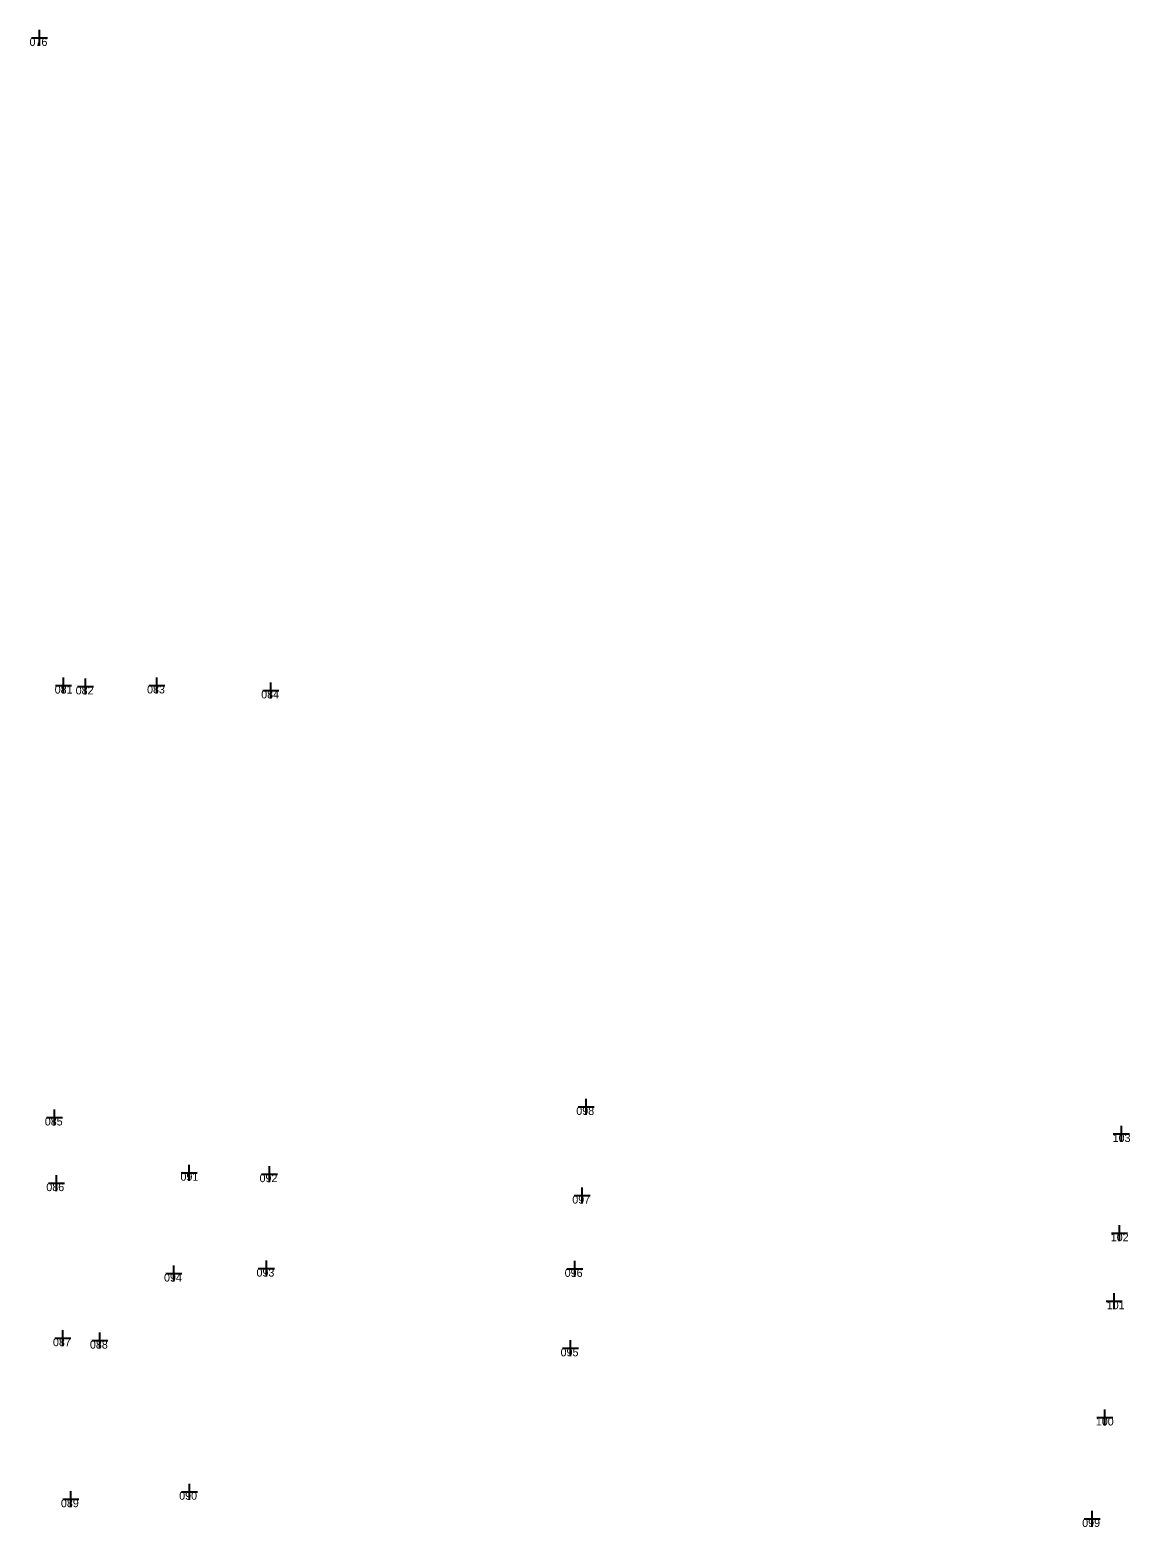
# Model space of a CAD drawing. Extents: x -706655 to -706193, y -1036183 to -1034979.
# Drawn here: x -706408.8 to -706340.1, y -1035526.2 to -1035432.7 of the extents above; entities that cross this region are included whole.
import ezdxf

# ---------------------------------------------------------------- set-up
doc = ezdxf.new("R2010")
doc.units = 0
doc.layers.add('čísla bodu', color=7, linetype='Continuous')

msp = doc.modelspace()

# ---------------------------------------------------------------- linework, layer by layer
at = {"layer": 'čísla bodu'}
for p, q in [((-706408.2, -1035433.66), (-706408.2, -1035432.66)), ((-706408.7, -1035433.16), (-706407.7, -1035433.16)), ((-706408.2, -1035433.16), (-706408.2, -1035433.16)), ((-706407.21, -1035473.62), (-706406.21, -1035473.62)), ((-706406.71, -1035474.12), (-706406.71, -1035473.12)), ((-706406.71, -1035473.62), (-706406.71, -1035473.62)), ((-706405.83, -1035473.67), (-706404.83, -1035473.67)), ((-706405.33, -1035474.17), (-706405.33, -1035473.17)), ((-706405.33, -1035473.67), (-706405.33, -1035473.67)), ((-706401.37, -1035473.61), (-706400.37, -1035473.61)), ((-706400.87, -1035474.11), (-706400.87, -1035473.11)), ((-706400.87, -1035473.61), (-706400.87, -1035473.61)), ((-706394.24, -1035473.92), (-706393.24, -1035473.92)), ((-706393.74, -1035474.42), (-706393.74, -1035473.42)), ((-706393.74, -1035473.92), (-706393.74, -1035473.92)), ((-706407.26, -1035501.1), (-706407.26, -1035500.1)), ((-706374.55, -1035499.94), (-706373.55, -1035499.94)), ((-706374.05, -1035500.44), (-706374.05, -1035499.44)), ((-706374.05, -1035499.94), (-706374.05, -1035499.94)), ((-706407.76, -1035500.6), (-706406.76, -1035500.6)), ((-706407.26, -1035500.6), (-706407.26, -1035500.6)), ((-706340.61, -1035502.13), (-706340.61, -1035501.13)), ((-706341.11, -1035501.63), (-706340.11, -1035501.63)), ((-706340.61, -1035501.63), (-706340.61, -1035501.63)), ((-706398.85, -1035504.55), (-706398.85, -1035503.55)), ((-706393.84, -1035504.64), (-706393.84, -1035503.64)), ((-706407.65, -1035504.7), (-706406.65, -1035504.7)), ((-706407.15, -1035505.2), (-706407.15, -1035504.2)), ((-706407.15, -1035504.7), (-706407.15, -1035504.7)), ((-706399.35, -1035504.05), (-706398.35, -1035504.05)), ((-706398.85, -1035504.05), (-706398.85, -1035504.05)), ((-706394.34, -1035504.14), (-706393.34, -1035504.14)), ((-706393.84, -1035504.14), (-706393.84, -1035504.14)), ((-706374.8, -1035505.48), (-706373.8, -1035505.48)), ((-706374.3, -1035505.98), (-706374.3, -1035504.98)), ((-706374.3, -1035505.48), (-706374.3, -1035505.48)), ((-706340.73, -1035508.33), (-706340.73, -1035507.33)), ((-706341.23, -1035507.83), (-706340.23, -1035507.83)), ((-706340.73, -1035507.83), (-706340.73, -1035507.83)), ((-706394.03, -1035510.54), (-706394.03, -1035509.54)), ((-706374.76, -1035510.56), (-706374.76, -1035509.56)), ((-706400.31, -1035510.35), (-706399.31, -1035510.35)), ((-706399.81, -1035510.85), (-706399.81, -1035509.85)), ((-706399.81, -1035510.35), (-706399.81, -1035510.35)), ((-706394.53, -1035510.04), (-706393.53, -1035510.04)), ((-706394.03, -1035510.04), (-706394.03, -1035510.04)), ((-706375.26, -1035510.06), (-706374.26, -1035510.06)), ((-706374.76, -1035510.06), (-706374.76, -1035510.06)), ((-706341.55, -1035512.08), (-706340.55, -1035512.08)), ((-706341.05, -1035512.58), (-706341.05, -1035511.58)), ((-706341.05, -1035512.08), (-706341.05, -1035512.08)), ((-706406.75, -1035514.89), (-706406.75, -1035513.89)), ((-706404.44, -1035515.04), (-706404.44, -1035514.04)), ((-706407.25, -1035514.39), (-706406.25, -1035514.39)), ((-706406.75, -1035514.39), (-706406.75, -1035514.39)), ((-706404.94, -1035514.54), (-706403.94, -1035514.54)), ((-706404.44, -1035514.54), (-706404.44, -1035514.54)), ((-706375.53, -1035515.02), (-706374.53, -1035515.02)), ((-706375.03, -1035515.52), (-706375.03, -1035514.52)), ((-706375.03, -1035515.02), (-706375.03, -1035515.02)), ((-706341.64, -1035519.84), (-706341.64, -1035518.84)), ((-706342.14, -1035519.34), (-706341.14, -1035519.34)), ((-706341.64, -1035519.34), (-706341.64, -1035519.34)), ((-706398.84, -1035524.48), (-706398.84, -1035523.48)), ((-706406.75, -1035524.45), (-706405.75, -1035524.45)), ((-706406.25, -1035524.95), (-706406.25, -1035523.95)), ((-706406.25, -1035524.45), (-706406.25, -1035524.45)), ((-706399.34, -1035523.98), (-706398.34, -1035523.98)), ((-706398.84, -1035523.98), (-706398.84, -1035523.98)), ((-706342.44, -1035526.18), (-706342.44, -1035525.18)), ((-706342.94, -1035525.68), (-706341.94, -1035525.68)), ((-706342.44, -1035525.68), (-706342.44, -1035525.68))]:
    msp.add_line(p, q, dxfattribs=at)

# ---------------------------------------------------------------- texts
for s, p in [('076', (-706408.826, -1035433.66)), ('081', (-706407.252, -1035474.12)), ('082', (-706405.942, -1035474.17)), ('083', (-706401.482, -1035474.11)), ('084', (-706394.352, -1035474.42)), ('098', (-706374.664, -1035500.44)), ('085', (-706407.872, -1035501.1)), ('103', (-706341.151, -1035502.13)), ('086', (-706407.776, -1035505.2)), ('091', (-706399.394, -1035504.55)), ('092', (-706394.454, -1035504.64)), ('097', (-706374.914, -1035505.98)), ('102', (-706341.271, -1035508.33)), ('094', (-706400.424, -1035510.85)), ('093', (-706394.644, -1035510.54)), ('096', (-706375.388, -1035510.56)), ('101', (-706341.522, -1035512.58)), ('087', (-706407.362, -1035514.89)), ('088', (-706405.052, -1035515.04)), ('095', (-706375.644, -1035515.52)), ('100', (-706342.203, -1035519.84)), ('089', (-706406.864, -1035524.95)), ('090', (-706399.476, -1035524.48)), ('099', (-706343.056, -1035526.18))]:
    msp.add_text(s, height=0.5, dxfattribs=at).set_placement(p)

doc.saveas('drawing.dxf')
